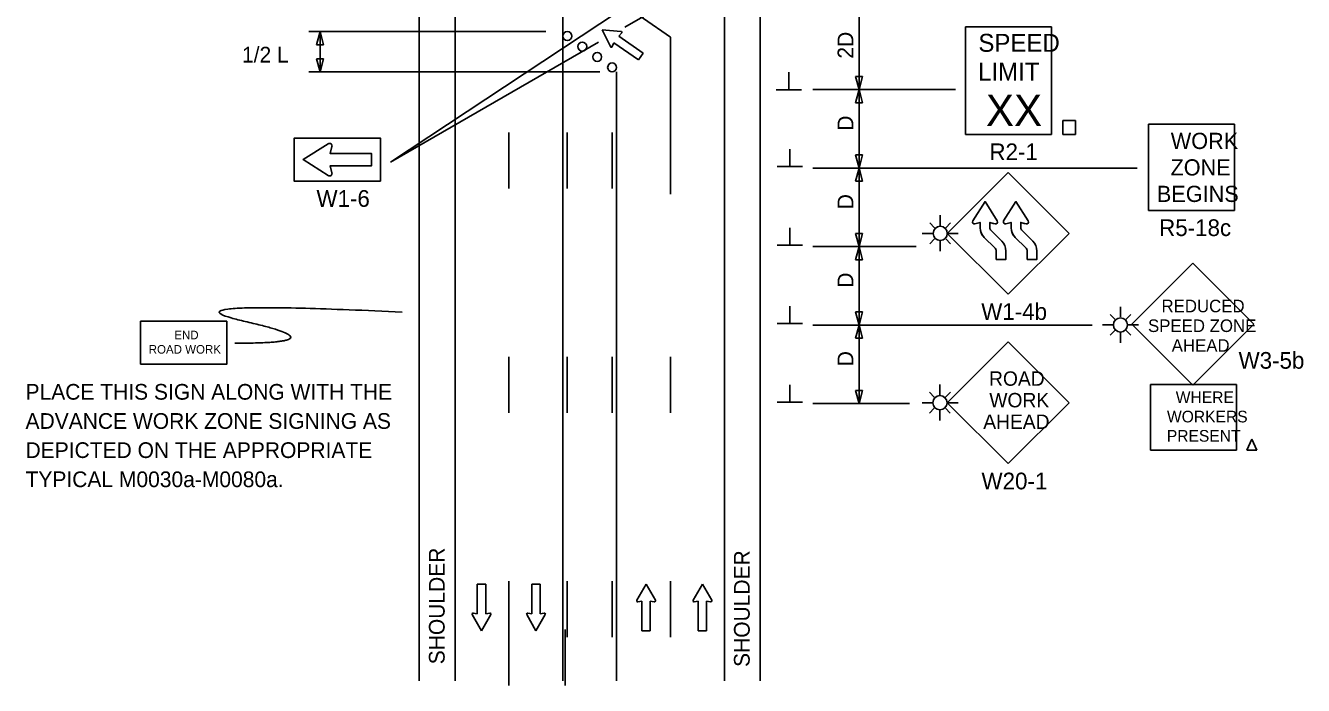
# Model space of a CAD drawing. Extents: x 16577 to 18475, y 5712 to 6909.
# Drawn here: x 16731 to 17301, y 6137 to 6432 of the extents above; entities that cross this region are included whole.
import ezdxf

# ---------------------------------------------------------------- set-up
doc = ezdxf.new("R2010")
doc.units = 0
for name, color, linetype in [('ALI_LEGAL_EX', 7, 'Continuous'), ('Level 3', 7, 'Continuous'), ('MT_SCRATCH_LEVEL_E', 7, 'Continuous'), ('PAVT_EDGE_EX', 7, 'Continuous'), ('TRAFFIC_SIGNS_PR', 7, 'Continuous'), ('TYPICAL_TEXT_DIMEN_PR', 7, 'Continuous')]:
    doc.layers.add(name, color=color, linetype=linetype)

msp = doc.modelspace()

# ---------------------------------------------------------------- linework, layer by layer
at = {"layer": 'ALI_LEGAL_EX'}
for points in [[(16946.75, 6383.94), (16946.75, 6358.94)], [(16972.75, 6383.94), (16972.75, 6358.94)], [(16992.75, 6383.94), (16992.75, 6358.94)], [(17018.75, 6383.94), (17018.75, 6358.94)], [(16946.75, 6283.94), (16946.75, 6258.94)], [(16972.75, 6283.94), (16972.75, 6258.94)], [(16992.75, 6283.94), (16992.75, 6258.94)], [(17018.75, 6283.94), (17018.75, 6258.94)], [(16946.75, 6183.94), (16946.75, 6158.94)], [(16946.75, 6183.94), (16946.75, 6158.94)], [(16972.75, 6183.94), (16972.75, 6158.94)], [(16992.75, 6183.94), (16992.75, 6158.94)], [(17018.75, 6183.94), (17018.75, 6158.94)]]:
    msp.add_lwpolyline(points, dxfattribs=at)
at = {"layer": 'Level 3'}
for p, q in [((17145.73, 6403.07), (17082.16, 6403.07)), ((17226.63, 6368.07), (17082.16, 6368.07)), ((17128.16, 6333.07), (17082.16, 6333.07)), ((17206.53, 6298.07), (17082.16, 6298.07)), ((17125.29, 6263.07), (17082.16, 6263.07))]:
    msp.add_line(p, q, dxfattribs=at)
at = {"layer": 'MT_SCRATCH_LEVEL_E'}
for p, q in [((16988.37, 6429.76), (16991.95, 6422.25)), ((16996.68, 6429.02), (16988.37, 6429.76)), ((16988.37, 6429.76), (16991.95, 6422.25)), ((16996.68, 6429.02), (16988.37, 6429.76)), ((16995.69, 6426.96), (16996.97, 6428.23)), ((16995.69, 6426.96), (16996.97, 6428.23)), ((16992.79, 6422.25), (16993.55, 6423.89)), ((16992.79, 6422.25), (16993.55, 6423.89)), ((16993.55, 6423.89), (17004.42, 6416.3)), ((16993.55, 6423.89), (17004.42, 6416.3)), ((17006.56, 6419.36), (16995.69, 6426.96)), ((17006.56, 6419.36), (16995.69, 6426.96)), ((17004.42, 6416.3), (17006.56, 6419.36)), ((17004.42, 6416.3), (17006.56, 6419.36)), ((16936.42, 6182.61), (16932.68, 6182.61)), ((16932.68, 6182.61), (16932.68, 6169.35)), ((16936.42, 6182.61), (16932.68, 6182.61)), ((16932.68, 6182.61), (16932.68, 6169.35)), ((16936.42, 6169.35), (16936.42, 6182.61)), ((16936.42, 6169.35), (16936.42, 6182.61)), ((16960.67, 6182.61), (16956.93, 6182.61)), ((16956.93, 6182.61), (16956.93, 6169.35)), ((16960.67, 6182.61), (16956.93, 6182.61)), ((16956.93, 6182.61), (16956.93, 6169.35)), ((16960.67, 6169.35), (16960.67, 6182.61)), ((16960.67, 6169.35), (16960.67, 6182.61)), ((17007.86, 6182.61), (17003.75, 6175.37)), ((17007.86, 6182.61), (17003.75, 6175.37)), ((17012.01, 6175.37), (17007.86, 6182.61)), ((17012.01, 6175.37), (17007.86, 6182.61)), ((17032.95, 6182.61), (17028.84, 6175.37)), ((17032.95, 6182.61), (17028.84, 6175.37)), ((17037.1, 6175.37), (17032.95, 6182.61)), ((17037.1, 6175.37), (17032.95, 6182.61)), ((17004.24, 6174.68), (17006.01, 6175)), ((17004.24, 6174.68), (17006.01, 6175)), ((17006.01, 6175), (17006.01, 6161.74)), ((17006.01, 6175), (17006.01, 6161.74)), ((17009.75, 6161.74), (17009.75, 6175)), ((17009.75, 6175), (17011.53, 6174.68)), ((17009.75, 6161.74), (17009.75, 6175)), ((17009.75, 6175), (17011.53, 6174.68)), ((17029.32, 6174.68), (17031.1, 6175)), ((17029.32, 6174.68), (17031.1, 6175)), ((17031.1, 6175), (17031.1, 6161.74)), ((17031.1, 6175), (17031.1, 6161.74)), ((17034.84, 6161.74), (17034.84, 6175)), ((17034.84, 6175), (17036.62, 6174.68)), ((17034.84, 6161.74), (17034.84, 6175)), ((17034.84, 6175), (17036.62, 6174.68)), ((16930.42, 6168.98), (16934.57, 6161.74)), ((16930.42, 6168.98), (16934.57, 6161.74)), ((16932.68, 6169.35), (16930.9, 6169.67)), ((16932.68, 6169.35), (16930.9, 6169.67)), ((16934.57, 6161.74), (16938.68, 6168.98)), ((16934.57, 6161.74), (16938.68, 6168.98)), ((16938.2, 6169.67), (16936.42, 6169.35)), ((16938.2, 6169.67), (16936.42, 6169.35)), ((16954.68, 6168.98), (16958.82, 6161.74)), ((16954.68, 6168.98), (16958.82, 6161.74)), ((16956.93, 6169.35), (16955.15, 6169.67)), ((16956.93, 6169.35), (16955.15, 6169.67)), ((16958.82, 6161.74), (16962.93, 6168.98)), ((16958.82, 6161.74), (16962.93, 6168.98)), ((16962.45, 6169.67), (16960.67, 6169.35)), ((16962.45, 6169.67), (16960.67, 6169.35)), ((17006.01, 6161.74), (17009.75, 6161.74)), ((17006.01, 6161.74), (17009.75, 6161.74)), ((17031.1, 6161.74), (17034.84, 6161.74)), ((17031.1, 6161.74), (17034.84, 6161.74))]:
    msp.add_line(p, q, dxfattribs=at)
for centre, start, end in [((16996.63, 6428.55), 315.105, 84.8419), ((16996.63, 6428.55), 315.105, 84.8419), ((16992.37, 6422.45), 205.4936, 335.0326), ((16992.37, 6422.45), 205.4936, 335.0326), ((17004.16, 6175.14), 150.4248, 279.9638), ((17004.16, 6175.14), 150.4248, 279.9638), ((17011.6, 6175.14), 260.0362, 29.7731), ((17011.6, 6175.14), 260.0362, 29.7731), ((17029.25, 6175.14), 150.4248, 279.9638), ((17029.25, 6175.14), 150.4248, 279.9638), ((17036.69, 6175.14), 260.0362, 29.7731), ((17036.69, 6175.14), 260.0362, 29.7731), ((16930.83, 6169.21), 80.0362, 209.7731), ((16930.83, 6169.21), 80.0362, 209.7731), ((16938.27, 6169.21), 330.4248, 99.9638), ((16938.27, 6169.21), 330.4248, 99.9638), ((16955.09, 6169.21), 80.0362, 209.7731), ((16955.09, 6169.21), 80.0362, 209.7731), ((16962.53, 6169.21), 330.4248, 99.9638), ((16962.53, 6169.21), 330.4248, 99.9638)]:
    msp.add_arc(centre, 0.463, start, end, dxfattribs=at)
at = {"layer": 'PAVT_EDGE_EX'}
for p, q in [((16906.75, 6901.43), (16906.75, 6139.45)), ((16922.75, 6901.43), (16922.75, 6139.45)), ((16970.75, 6901.43), (16970.75, 6139.45)), ((17042.75, 6901.43), (17042.75, 6139.45)), ((17058.75, 6901.43), (17058.75, 6139.45)), ((16994.75, 6443.28), (17018.75, 6426.52)), ((17018.75, 6426.52), (17018.75, 6356.47)), ((16994.75, 6410.96), (16994.75, 6139.45))]:
    msp.add_line(p, q, dxfattribs=at)
for points in [[(16946.75, 6137.4), (16946.75, 6162.4)], [(16971.75, 6137.4), (16971.75, 6162.4)]]:
    msp.add_lwpolyline(points, dxfattribs=at)
at = {"layer": 'TRAFFIC_SIGNS_PR'}
for p, q in [((17150.14, 6431.06), (17188.54, 6431.06)), ((17150.14, 6383.06), (17150.14, 6431.06)), ((17188.54, 6383.06), (17188.54, 6431.06)), ((17231.62, 6349.22), (17231.62, 6387.62)), ((17231.62, 6387.62), (17270.02, 6387.62)), ((17270.02, 6349.22), (17270.02, 6387.62)), ((17150.14, 6383.06), (17188.54, 6383.06)), ((16866.25, 6378.94), (16855.09, 6371.84)), ((16867.1, 6374.64), (16867.94, 6377.7)), ((16855.09, 6371.84), (16866.25, 6364.73)), ((16885.49, 6374.64), (16867.1, 6374.64)), ((16885.49, 6374.64), (16885.49, 6369.04)), ((16867.94, 6365.98), (16867.1, 6369.04)), ((16867.1, 6369.04), (16885.49, 6369.04)), ((17142.07, 6338.97), (17169.22, 6366.13)), ((17169.22, 6366.13), (17196.38, 6338.97)), ((17231.62, 6349.22), (17270.02, 6349.22)), ((17136.4, 6341.49), (17134.3, 6343.6)), ((17138.92, 6342.53), (17138.92, 6347.03)), ((17141.43, 6341.49), (17143.54, 6343.6)), ((17135.76, 6338.98), (17130.93, 6338.98)), ((17136.4, 6336.46), (17134.3, 6334.35)), ((17141.43, 6336.46), (17143.54, 6334.36)), ((17142.07, 6338.98), (17146.95, 6338.98)), ((17169.22, 6311.82), (17142.07, 6338.97)), ((17163.24, 6332.46), (17158.53, 6337.17)), ((17163.24, 6332.46), (17158.53, 6337.17)), ((17166.29, 6335.51), (17161.58, 6340.22)), ((17161.58, 6340.22), (17166.29, 6335.51)), ((17196.38, 6338.97), (17169.22, 6311.82)), ((17177.04, 6332.46), (17172.32, 6337.17)), ((17177.04, 6332.46), (17172.32, 6337.17)), ((17180.09, 6335.51), (17175.38, 6340.22)), ((17175.38, 6340.22), (17180.09, 6335.51)), ((17138.92, 6331.01), (17138.92, 6335.42)), ((17163.84, 6327.39), (17163.84, 6331.09)), ((17168.16, 6327.39), (17168.16, 6331.09)), ((17177.64, 6327.39), (17177.64, 6331.09)), ((17181.96, 6327.39), (17181.96, 6331.09)), ((17168.16, 6327.39), (17163.84, 6327.39)), ((17181.96, 6327.39), (17177.64, 6327.39)), ((17251.42, 6325.63), (17224.27, 6298.48)), ((17278.57, 6298.48), (17251.42, 6325.63)), ((17216.68, 6300.65), (17214.57, 6302.76)), ((17219.19, 6301.69), (17219.19, 6306.2)), ((17221.7, 6300.65), (17223.81, 6302.76)), ((17216.04, 6298.14), (17211.2, 6298.14)), ((17222.34, 6298.14), (17227.23, 6298.14)), ((17224.27, 6298.48), (17251.42, 6271.33)), ((17251.42, 6271.33), (17278.57, 6298.48)), ((17216.68, 6295.63), (17214.57, 6293.52)), ((17219.19, 6290.17), (17219.19, 6294.58)), ((17221.7, 6295.63), (17223.81, 6293.52)), ((17169.14, 6290.67), (17141.95, 6263.48)), ((17196.32, 6263.48), (17169.14, 6290.67)), ((17136.28, 6265.99), (17134.17, 6268.1)), ((17138.79, 6267.04), (17138.79, 6271.54)), ((17141.31, 6265.99), (17143.42, 6268.1)), ((17232.53, 6271.6), (17270.93, 6271.6)), ((17232.53, 6242.29), (17232.53, 6271.6)), ((17270.93, 6242.29), (17270.93, 6271.6)), ((17135.64, 6263.48), (17130.8, 6263.48)), ((17141.95, 6263.48), (17169.14, 6236.29)), ((17141.95, 6263.48), (17146.83, 6263.48)), ((17169.14, 6236.29), (17196.32, 6263.48)), ((17136.28, 6260.97), (17134.17, 6258.86)), ((17138.79, 6255.52), (17138.79, 6259.93)), ((17141.31, 6260.97), (17143.41, 6258.86)), ((17232.53, 6242.29), (17270.93, 6242.29))]:
    msp.add_line(p, q, dxfattribs=at)
for points in [[(17193.56, 6383.06), (17199.15, 6383.06), (17199.15, 6389.23), (17193.56, 6389.23)], [(16889.49, 6362.24), (16851.09, 6362.24), (16851.09, 6381.44), (16889.49, 6381.44)], [(16782.69, 6280.6), (16821.09, 6280.6), (16821.09, 6299.8), (16782.69, 6299.8)]]:
    msp.add_lwpolyline(points, close=True, dxfattribs=at)
for points in [[(16866.25, 6364.73), (16855.09, 6371.84), (16866.25, 6378.94)], [(16867.94, 6377.7), (16867.1, 6374.64), (16885.49, 6374.64), (16885.49, 6369.04), (16867.1, 6369.04), (16867.94, 6365.98)], [(17153.37, 6344.5), (17158.86, 6353.11), (17164.34, 6344.5)], [(17153.38, 6344.5), (17158.86, 6353.11), (17164.34, 6344.5)], [(17167.17, 6344.5), (17172.65, 6353.11), (17178.13, 6344.5)], [(17167.17, 6344.5), (17172.65, 6353.11), (17178.13, 6344.5)], [(17156.71, 6341.48), (17156.7, 6343.85), (17154.34, 6343.2)], [(17156.71, 6341.48), (17156.7, 6343.85), (17154.34, 6343.2)], [(17163.38, 6343.2), (17161.02, 6343.85), (17161.02, 6341.55)], [(17163.38, 6343.2), (17162.54, 6343.43), (17161.02, 6343.85), (17161.02, 6341.55)], [(17170.5, 6341.48), (17170.5, 6343.85), (17168.13, 6343.2)], [(17170.5, 6341.48), (17170.5, 6343.85), (17168.13, 6343.2)], [(17177.17, 6343.2), (17174.81, 6343.85), (17174.82, 6341.55)], [(17177.17, 6343.2), (17176.34, 6343.43), (17174.81, 6343.85), (17174.82, 6341.55)], [(17168.16, 6331.09), (17168.16, 6327.39), (17163.84, 6327.39), (17163.84, 6331.09)], [(17181.96, 6331.09), (17181.96, 6327.39), (17177.64, 6327.39), (17177.64, 6331.09)], [(17277.68, 6247.23), (17275.44, 6242.29)], [(17275.44, 6242.29), (17277.68, 6247.23)], [(17279.92, 6242.29), (17277.68, 6247.23)], [(17277.68, 6247.23), (17279.92, 6242.29)], [(17275.44, 6242.29), (17279.92, 6242.29)], [(17279.92, 6242.29), (17275.44, 6242.29)]]:
    msp.add_lwpolyline(points, dxfattribs=at)
for centre, radius in [((16972.75, 6426.93), 2), ((16972.75, 6426.93), 2), ((16979.42, 6422.27), 2), ((16986.08, 6417.62), 2), ((16992.75, 6412.96), 2), ((17138.92, 6338.98), 3.15), ((17219.19, 6298.14), 3.15), ((17138.79, 6263.48), 3.15)]:
    msp.add_circle(centre, radius, dxfattribs=at)
for centre, radius, start, end in [((16866.86, 6377.99), 1.12, 344.6731, 122.4696), ((16866.86, 6377.99), 1.12, 344.6731, 122.4696), ((16866.86, 6365.68), 1.12, 237.5304, 15.3269), ((16866.86, 6365.68), 1.12, 237.5304, 15.3269), ((17154.11, 6344.04), 0.866, 147.7292, 285.3172), ((17154.11, 6344.04), 0.866, 147.7196, 285.3201), ((17144.27, 6350.29), 10.8, 327.5335, 327.5431), ((17157.19, 6332.78), 10.8, 105.3192, 105.32), ((17163.61, 6344.03), 0.864, 254.6014, 32.4796), ((17163.61, 6344.03), 0.866, 254.6148, 32.4712), ((17167.9, 6344.04), 0.866, 147.7292, 285.3172), ((17167.9, 6344.04), 0.866, 147.7196, 285.3201), ((17158.06, 6350.29), 10.8, 327.5335, 327.5431), ((17170.99, 6332.78), 10.8, 105.3192, 105.32), ((17177.4, 6344.03), 0.864, 254.6014, 32.4796), ((17177.4, 6344.03), 0.866, 254.6148, 32.4712), ((17162.87, 6341.55), 6.17, 180.6181, 225.7875), ((17162.87, 6341.55), 6.17, 180.6245, 225.2313), ((17162.87, 6341.55), 1.85, 180, 225.7875), ((17162.87, 6341.55), 1.85, 179.8762, 225.7877), ((17176.67, 6341.55), 6.17, 180.6181, 225.7875), ((17176.67, 6341.55), 6.17, 180.6245, 225.2313), ((17176.67, 6341.55), 1.85, 180, 225.7875), ((17176.67, 6341.55), 1.85, 179.8762, 225.7877), ((17161.99, 6331.09), 1.85, 0, 47.628), ((17162, 6331.09), 1.85, 0, 45.7875), ((17162, 6331.09), 6.17, 0, 45.7875), ((17162, 6331.09), 6.17, 0, 45.7875), ((17161.99, 6331.09), 6.17, 0, 45.7883), ((17175.79, 6331.09), 1.85, 0, 47.628), ((17175.79, 6331.09), 1.85, 0, 45.7875), ((17175.79, 6331.09), 6.17, 0, 45.7875), ((17175.79, 6331.09), 6.17, 0, 45.7875), ((17175.79, 6331.09), 6.17, 0, 45.7883)]:
    msp.add_arc(centre, radius, start, end, dxfattribs=at)
msp.add_open_spline([(16824.68, 6289.98), (16871.92, 6289.98), (16786.89, 6309.33), (16899.19, 6303.84)], degree=2, dxfattribs=at)
at = {"layer": 'TYPICAL_TEXT_DIMEN_PR'}
for p, q in [((17004.32, 6443.85), (16894.07, 6370.79)), ((16998.42, 6430.97), (17013.38, 6439.6)), ((17102.75, 6403.07), (17102.75, 6438.07)), ((16857.65, 6428.93), (16963.28, 6428.93)), ((16861.08, 6423.07), (16862.65, 6428.93)), ((16862.65, 6410.96), (16862.65, 6428.93)), ((16862.65, 6428.93), (16864.22, 6423.07)), ((16862.65, 6423.07), (16861.08, 6423.07)), ((16864.22, 6423.07), (16862.65, 6423.07)), ((16894.07, 6370.79), (16986.71, 6424.21)), ((16862.65, 6410.96), (16861.08, 6416.82)), ((16861.08, 6416.82), (16862.65, 6416.82)), ((16862.65, 6416.82), (16864.22, 6416.82)), ((16864.22, 6416.82), (16862.65, 6410.96)), ((16857.65, 6410.96), (16987.28, 6410.96)), ((17071.5, 6403.02), (17071.5, 6410.81)), ((17102.75, 6403.07), (17101.18, 6408.94)), ((17101.18, 6408.94), (17102.75, 6408.94)), ((17102.75, 6408.94), (17104.32, 6408.94)), ((17104.32, 6408.94), (17102.75, 6403.07)), ((17077.13, 6403.02), (17065.88, 6403.02)), ((17101.18, 6397.21), (17102.75, 6403.07)), ((17102.75, 6403.07), (17104.32, 6397.21)), ((17102.75, 6403.07), (17102.75, 6368.07)), ((17102.75, 6397.21), (17101.18, 6397.21)), ((17104.32, 6397.21), (17102.75, 6397.21)), ((17071.87, 6368.72), (17071.87, 6376.5)), ((17102.75, 6368.07), (17101.18, 6373.94)), ((17101.18, 6373.94), (17102.75, 6373.94)), ((17102.75, 6373.94), (17104.32, 6373.94)), ((17104.32, 6373.94), (17102.75, 6368.07)), ((17077.5, 6368.72), (17066.25, 6368.72)), ((17101.18, 6362.21), (17102.75, 6368.07)), ((17102.75, 6368.07), (17104.32, 6362.21)), ((17102.75, 6368.07), (17102.75, 6333.07)), ((17102.75, 6362.21), (17101.18, 6362.21)), ((17104.32, 6362.21), (17102.75, 6362.21)), ((17071.87, 6333.72), (17071.87, 6341.5)), ((17102.75, 6333.07), (17101.18, 6338.94)), ((17101.18, 6338.94), (17102.75, 6338.94)), ((17102.75, 6338.94), (17104.32, 6338.94)), ((17104.32, 6338.94), (17102.75, 6333.07)), ((17077.5, 6333.72), (17066.25, 6333.72)), ((17101.18, 6327.21), (17102.75, 6333.07)), ((17102.75, 6333.07), (17104.32, 6327.21)), ((17102.75, 6333.07), (17102.75, 6298.07)), ((17102.75, 6327.21), (17101.18, 6327.21)), ((17104.32, 6327.21), (17102.75, 6327.21)), ((17071.87, 6298.72), (17071.87, 6306.5)), ((17102.75, 6298.07), (17101.18, 6303.94)), ((17101.18, 6303.94), (17102.75, 6303.94)), ((17102.75, 6303.94), (17104.32, 6303.94)), ((17104.32, 6303.94), (17102.75, 6298.07)), ((17077.5, 6298.72), (17066.25, 6298.72)), ((17101.18, 6292.21), (17102.75, 6298.07)), ((17102.75, 6298.07), (17104.32, 6292.21)), ((17102.75, 6298.07), (17102.75, 6263.07)), ((17102.75, 6292.21), (17101.18, 6292.21)), ((17104.32, 6292.21), (17102.75, 6292.21)), ((17071.87, 6263.72), (17071.87, 6271.5)), ((17102.75, 6263.07), (17101.18, 6268.94)), ((17101.18, 6268.94), (17102.75, 6268.94)), ((17102.75, 6268.94), (17104.32, 6268.94)), ((17104.32, 6268.94), (17102.75, 6263.07)), ((17077.5, 6263.72), (17066.25, 6263.72))]:
    msp.add_line(p, q, dxfattribs=at)

# ---------------------------------------------------------------- texts
at = {"layer": 'TRAFFIC_SIGNS_PR'}
for s, height, p in [('SPEED', 8, (17155.91, 6419.92)), ('LIMIT', 8, (17155.75, 6407.12)), ('XX', 14.031, (17159.26, 6386.81)), ('WORK', 7.217, (17241.62, 6376.59)), ('R2-1', 7.44, (17160.82, 6371.62)), ('ZONE', 7.217, (17241.5, 6364.78)), ('BEGINS', 7.217, (17235.43, 6352.97)), ('W1-6', 7.44, (16861.03, 6350.8)), ('R5-18c', 7.44, (17236.43, 6337.78)), ('W1-4b', 7.44, (17157.18, 6300.38)), ('REDUCED', 5.6, (17237.48, 6303.79)), ('SPEED ZONE', 5.6, (17231.47, 6294.99)), ('END', 3.831, (16797.69, 6291.73)), ('AHEAD', 5.6, (17242.03, 6286.19)), ('ROAD WORK', 3.831, (16786.3, 6285.35)), ('W3-5b', 7.44, (17271.83, 6278.62)), ('ROAD', 6.408, (17160.67, 6271.03)), ('PLACE THIS SIGN ALONG WITH THE', 7, (16731.41, 6264.82)), ('WHERE', 5.2, (17243.84, 6263.29)), ('WORK', 6.408, (17160.78, 6261.41)), ('ADVANCE WORK ZONE SIGNING AS', 7, (16731.41, 6251.82)), ('AHEAD', 6.408, (17158.08, 6251.8)), ('WORKERS', 5.2, (17239.92, 6254.69)), ('PRESENT', 5.2, (17239.85, 6246.09)), ('DEPICTED ON THE APPROPRIATE', 7, (16731.41, 6238.82)), ('TYPICAL M0030a-M0080a.', 7, (16731.41, 6225.82)), ('W20-1', 7.449, (17157.29, 6224.84))]:
    msp.add_text(s, height=height, dxfattribs=at).set_placement(p)
at = {"layer": 'TYPICAL_TEXT_DIMEN_PR'}
for s, p in [('2D', (17100.19, 6416.89)), ('D', (17100.19, 6384.72)), ('D', (17100.19, 6349.72)), ('D', (17100.19, 6314.72)), ('D', (17100.19, 6279.72)), ('SHOULDER', (16918.13, 6146.85)), ('SHOULDER', (17054.03, 6145.66))]:
    msp.add_text(s, height=7, rotation=90, dxfattribs=at).set_placement(p)
msp.add_text('1/2 L', height=7, dxfattribs=at).set_placement((16827.85, 6415.15))

doc.saveas('drawing.dxf')
